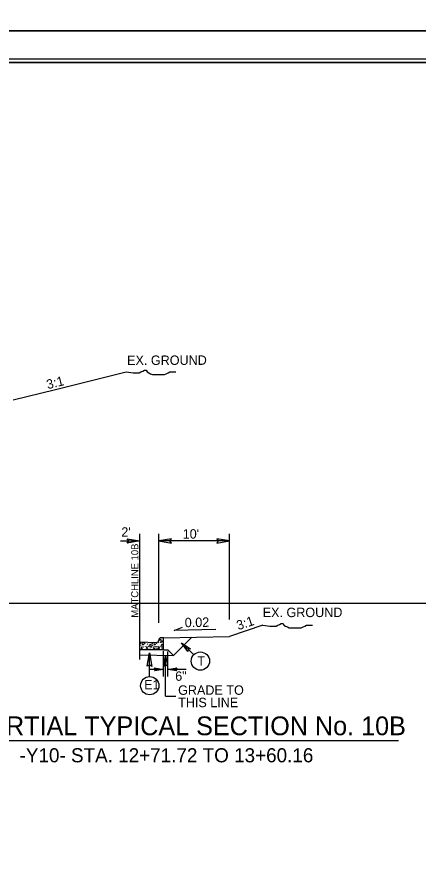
# Model space of a CAD drawing. Extents: x 2320980 to 2456309, y 595047 to 606177.
# Drawn here: x 2455919.1 to 2455975.9, y 596187.4 to 596305.6 of the extents above; entities that cross this region are included whole.
import ezdxf

# ---------------------------------------------------------------- set-up
doc = ezdxf.new("R2010")
doc.units = 0
for name, color, linetype in [('Matchline Text', 7, 'Continuous'), ('Old_Level_1', 7, 'Continuous'), ('Old_Level_2', 7, 'Continuous'), ('Old_Level_20', 7, 'Continuous'), ('Old_Level_21', 7, 'Continuous'), ('Old_Level_3', 7, 'Continuous'), ('Prop Dimension Text', 7, 'Continuous'), ('Sheet Cutting Line CELL', 7, 'Continuous'), ('Sheet Plan CELL', 7, 'Continuous'), ('Sheet Plot Border Inside CELL', 7, 'Continuous'), ('Sheet Plot Border Outside CELL', 7, 'Continuous'), ('Typical Berm CELL', 7, 'Continuous'), ('Typical Curb CELL', 7, 'Continuous'), ('Typical Hinge Slope Arterial CELL', 7, 'Continuous'), ('Typical ID Circle CELL', 7, 'Continuous'), ('Typical Pavement Slope CELL', 7, 'Continuous'), ('Typical Terminator CELL', 7, 'Continuous')]:
    doc.layers.add(name, color=color, linetype=linetype)

msp = doc.modelspace()

# ---------------------------------------------------------------- linework, layer by layer
at = {"layer": 'Old_Level_21'}
for p, q in [((2455936.51, 596214.64), (2455936.51, 596232.44)), ((2455939.17, 596219.83), (2455939.17, 596232.44)), ((2455949.17, 596220.32), (2455949.17, 596232.44)), ((2455933.76, 596231.43), (2455936.51, 596231.43)), ((2455949.17, 596231.43), (2455939.17, 596231.43)), ((2455953.9, 596219.51), (2455949.17, 596217.93)), ((2455939.83, 596212.25), (2455939.83, 596215.84)), ((2455940.46, 596212.25), (2455940.46, 596215.8)), ((2455940.13, 596209.48), (2455941.58, 596209.48))]:
    msp.add_line(p, q, dxfattribs=at)
at = {"layer": 'Old_Level_3'}
msp.add_line((2455913.5, 596203.22), (2455973.08, 596203.22), dxfattribs=at)
at = {"layer": 'Prop Dimension Text'}
for p, q in [((2455944.13, 596215.34), (2455942.37, 596217.02)), ((2455940.13, 596209.48), (2455940.13, 596215.24)), ((2455939.83, 596213.26), (2455937.94, 596213.26)), ((2455943.03, 596213.26), (2455940.46, 596213.26))]:
    msp.add_line(p, q, dxfattribs=at)
msp.add_lwpolyline([(2455947.23, 596218.92), (2455941.37, 596218.76), (2455942.51, 596219.25)], dxfattribs=at)
for centre in [(2455945.06, 596214.44), (2455937.9, 596210.96)]:
    msp.add_circle(centre, 1.29, dxfattribs=at)
at = {"layer": 'Sheet Cutting Line CELL'}
msp.add_line((2456045.51, 596222.57), (2455708.81, 596222.57), dxfattribs=at)
at = {"layer": 'Sheet Plan CELL'}
for points in [[(2456042.11, 596299.08), (2455742.1, 596299.08), (2455742.1, 596089.08), (2456042.11, 596089.08)], [(2455742.1, 596089.08), (2455742.1, 596299.07), (2456002.1, 596299.08), (2456002.1, 596269.07), (2456042.11, 596269.06), (2456042.11, 596089.08)]]:
    msp.add_lwpolyline(points, close=True, dxfattribs=at)
at = {"layer": 'Sheet Plot Border Inside CELL'}
msp.add_lwpolyline([(2455711.41, 596088.57), (2456044.6, 596088.58), (2456044.61, 596299.57), (2455711.41, 596299.57)], close=True, dxfattribs=at)
at = {"layer": 'Sheet Plot Border Outside CELL'}
for points in [[(2455708.81, 596303.57), (2456045.51, 596303.57), (2456045.51, 596522.57), (2455708.81, 596522.57)], [(2455708.81, 596084.57), (2456045.51, 596084.57), (2456045.51, 596303.57), (2455708.81, 596303.57)]]:
    msp.add_lwpolyline(points, close=True, dxfattribs=at)
at = {"layer": 'Typical Berm CELL'}
for p, q in [((2455939.83, 596217.74), (2455949.17, 596217.93)), ((2455939.83, 596216.02), (2455940.45, 596216.02))]:
    msp.add_line(p, q, dxfattribs=at)
at = {"layer": 'Typical Curb CELL'}
for p, q in [((2455936.51, 596217.18), (2455938.83, 596217.09)), ((2455936.85, 596216.73), (2455936.97, 596216.88)), ((2455936.97, 596216.88), (2455937.01, 596216.73)), ((2455938.51, 596216.73), (2455938.63, 596216.88)), ((2455938.63, 596216.88), (2455938.67, 596216.73)), ((2455939.17, 596217.4), (2455939.17, 596217.42)), ((2455939.28, 596217.38), (2455939.36, 596217.54)), ((2455939.5, 596217.44), (2455939.28, 596217.38)), ((2455939.36, 596217.54), (2455939.5, 596217.44)), ((2455939.83, 596217.74), (2455939.48, 596217.74)), ((2455939.58, 596217.29), (2455939.6, 596217.17)), ((2455939.78, 596217.23), (2455939.58, 596217.29)), ((2455939.6, 596217.17), (2455939.78, 596217.23)), ((2455939.83, 596216.02), (2455939.83, 596217.74)), ((2455939.83, 596216.02), (2455936.51, 596216.02)), ((2455936.64, 596216.12), (2455936.76, 596216.28)), ((2455936.8, 596216.13), (2455936.64, 596216.12)), ((2455936.76, 596216.28), (2455936.8, 596216.13)), ((2455937.01, 596216.73), (2455936.85, 596216.73)), ((2455937.43, 596216.22), (2455937.54, 596216.38)), ((2455937.59, 596216.22), (2455937.43, 596216.22)), ((2455937.54, 596216.38), (2455937.59, 596216.22)), ((2455937.87, 596216.66), (2455937.95, 596216.81)), ((2455938.09, 596216.71), (2455937.87, 596216.66)), ((2455937.95, 596216.81), (2455938.09, 596216.71)), ((2455938.45, 596216.15), (2455938.53, 596216.3)), ((2455938.67, 596216.2), (2455938.45, 596216.15)), ((2455938.67, 596216.73), (2455938.51, 596216.73)), ((2455938.53, 596216.3), (2455938.67, 596216.2)), ((2455939.09, 596216.22), (2455939.21, 596216.38)), ((2455939.25, 596216.22), (2455939.09, 596216.22)), ((2455939.21, 596216.38), (2455939.25, 596216.22)), ((2455939.53, 596216.66), (2455939.61, 596216.81)), ((2455939.75, 596216.71), (2455939.53, 596216.66)), ((2455939.61, 596216.81), (2455939.75, 596216.71))]:
    msp.add_line(p, q, dxfattribs=at)
for centre in [(2455936.53, 596216.85), (2455936.55, 596216.98), (2455936.62, 596216.94), (2455936.77, 596217.1), (2455936.9, 596216.99), (2455936.96, 596217.13), (2455937.16, 596217.04), (2455937.19, 596216.91), (2455937.43, 596217.02), (2455937.45, 596217.09), (2455937.56, 596216.83), (2455937.79, 596217.05), (2455937.95, 596216.98), (2455938.19, 596216.85), (2455938.21, 596216.98), (2455938.29, 596216.94), (2455938.43, 596217.05), (2455938.56, 596216.99), (2455938.82, 596217.04), (2455938.86, 596216.91), (2455939.09, 596217.02), (2455939.11, 596217.09), (2455939.22, 596216.83), (2455939.24, 596217.26), (2455939.4, 596217.2), (2455939.46, 596217.05), (2455939.52, 596217.64), (2455939.61, 596216.98), (2455939.74, 596217.35), (2455939.81, 596217.59), (2455936.52, 596216.44), (2455936.6, 596216.66), (2455936.72, 596216.35), (2455936.73, 596216.73), (2455936.8, 596216.41), (2455936.96, 596216.43), (2455936.98, 596216.31), (2455937.01, 596216.51), (2455937.29, 596216.48), (2455937.31, 596216.22), (2455937.39, 596216.79), (2455937.44, 596216.59), (2455937.51, 596216.44), (2455937.75, 596216.52), (2455937.77, 596216.4), (2455937.97, 596216.28), (2455937.98, 596216.47), (2455938.01, 596216.08), (2455938.14, 596216.32), (2455938.18, 596216.44), (2455938.26, 596216.66), (2455938.39, 596216.73), (2455938.46, 596216.41), (2455938.53, 596216.47), (2455938.67, 596216.51), (2455938.77, 596216.35), (2455938.79, 596216.47), (2455938.84, 596216.16), (2455938.86, 596216.43), (2455938.95, 596216.48), (2455938.97, 596216.22), (2455939.05, 596216.79), (2455939.1, 596216.59), (2455939.17, 596216.44), (2455939.41, 596216.52), (2455939.43, 596216.4), (2455939.63, 596216.28), (2455939.64, 596216.47), (2455939.68, 596216.08), (2455939.8, 596216.32)]:
    msp.add_circle(centre, 0.0107, dxfattribs=at)
for centre, start, end in [((2455938.85, 596217.4), 267.6155, 360), ((2455939.48, 596217.42), 90, 180)]:
    msp.add_arc(centre, 0.319, start, end, dxfattribs=at)
at = {"layer": 'Typical Hinge Slope Arterial CELL'}
for p, q in [((2455934.56, 596255.32), (2455924.57, 596252.82)), ((2455924.57, 596252.82), (2455918.57, 596251.32))]:
    msp.add_line(p, q, dxfattribs=at)
for points in [[(2455934.57, 596255.33), (2455935.55, 596255.2), (2455935.8, 596255.2), (2455936.17, 596255.2), (2455936.42, 596255.2), (2455936.66, 596255.33), (2455936.91, 596255.45), (2455937.16, 596255.57), (2455937.4, 596255.57), (2455937.53, 596255.33), (2455937.77, 596255.2), (2455938.02, 596255.08), (2455938.27, 596254.96), (2455938.51, 596254.96), (2455938.76, 596254.96), (2455939, 596254.96), (2455939.25, 596254.96), (2455939.5, 596254.96), (2455939.74, 596254.96), (2455939.99, 596254.96), (2455940.24, 596255.08), (2455940.48, 596255.2), (2455940.73, 596255.33), (2455941.1, 596255.33), (2455941.35, 596255.33), (2455941.59, 596255.33)], [(2455953.9, 596219.51), (2455954.89, 596219.39), (2455955.13, 596219.39), (2455955.5, 596219.39), (2455955.75, 596219.39), (2455956, 596219.51), (2455956.24, 596219.63), (2455956.49, 596219.76), (2455956.74, 596219.76), (2455956.86, 596219.51), (2455957.11, 596219.39), (2455957.35, 596219.26), (2455957.6, 596219.14), (2455957.85, 596219.14), (2455958.09, 596219.14), (2455958.34, 596219.14), (2455958.58, 596219.14), (2455958.83, 596219.14), (2455959.08, 596219.14), (2455959.32, 596219.14), (2455959.57, 596219.26), (2455959.82, 596219.39), (2455960.06, 596219.51), (2455960.43, 596219.51), (2455960.68, 596219.51), (2455960.93, 596219.51)]]:
    msp.add_lwpolyline(points, dxfattribs=at)
at = {"layer": 'Typical ID Circle CELL'}
msp.add_line((2455937.87, 596212.26), (2455937.87, 596215.6), dxfattribs=at)
at = {"layer": 'Typical Pavement Slope CELL'}
for p, q in [((2455943.87, 596217.82), (2455941.26, 596215.21)), ((2455949.17, 596217.93), (2455949.17, 596217.93)), ((2455940.45, 596216.02), (2455941.26, 596215.21)), ((2455936.51, 596215.31), (2455941.26, 596215.21))]:
    msp.add_line(p, q, dxfattribs=at)
at = {"layer": 'Typical Terminator CELL'}
for points in [[(2455934.71, 596231.74), (2455936.51, 596231.43), (2455934.7, 596231.11), (2455934.93, 596231.43)], [(2455940.96, 596231.74), (2455939.17, 596231.43), (2455940.97, 596231.11), (2455940.74, 596231.43)], [(2455947.37, 596231.12), (2455949.17, 596231.43), (2455947.36, 596231.75), (2455947.59, 596231.43)], [(2455943.27, 596215.8), (2455942.37, 596217.02), (2455943.64, 596216.17), (2455943.32, 596216.11)], [(2455937.55, 596213.7), (2455937.87, 596215.6), (2455938.21, 596213.69), (2455937.87, 596213.93)], [(2455939.87, 596213.74), (2455940.13, 596215.24), (2455940.39, 596213.73), (2455940.13, 596213.92)], [(2455938.58, 596213.48), (2455939.83, 596213.26), (2455938.58, 596213.04), (2455938.74, 596213.26)], [(2455941.71, 596213.05), (2455940.46, 596213.26), (2455941.72, 596213.49), (2455941.56, 596213.26)]]:
    msp.add_lwpolyline(points, close=True, dxfattribs=at)

# ---------------------------------------------------------------- texts
at = {"layer": 'Matchline Text'}
msp.add_text('MATCHLINE 10B', height=1, rotation=90, dxfattribs=at).set_placement((2455936.28, 596220.58))
at = {"layer": 'Old_Level_1'}
for p in [(2455934.7, 596256.32), (2455953.87, 596220.65)]:
    msp.add_text('EX. GROUND', height=1.33, rotation=0.0897, dxfattribs=at).set_placement(p)
at = {"layer": 'Old_Level_2'}
for s, height, p in [('PARTIAL TYPICAL SECTION No. 10B', 2.66, (2455912.83, 596203.95)), ('-Y10- STA. 12+71.72 TO 13+60.16', 1.995, (2455919.5, 596200.12))]:
    msp.add_text(s, height=height, dxfattribs=at).set_placement(p)
at = {"layer": 'Old_Level_20'}
for s, p in [('T', (2455944.63, 596213.78)), ('E1', (2455937.11, 596210.43))]:
    msp.add_text(s, height=1.33, dxfattribs=at).set_placement(p)
at = {"layer": 'Old_Level_21'}
for s, rotation, p in [("2'", 0.0002, (2455933.88, 596232.03)), ('0.02', 1.1456, (2455942.86, 596219.22)), ('3:1', 18.4349, (2455950.42, 596218.8))]:
    msp.add_text(s, height=1.33, rotation=rotation, dxfattribs=at).set_placement(p)
for s, p in [("10'", (2455942.56, 596231.76)), ('6"', (2455941.5, 596211.65)), ('GRADE TO', (2455941.91, 596209.67)), ('THIS LINE', (2455941.91, 596207.92))]:
    msp.add_text(s, height=1.33, dxfattribs=at).set_placement(p)
at = {"layer": 'Typical Hinge Slope Arterial CELL'}
msp.add_text('3:1', height=1.33, rotation=14.0362, dxfattribs=at).set_placement((2455923.48, 596252.88))

doc.saveas('drawing.dxf')
